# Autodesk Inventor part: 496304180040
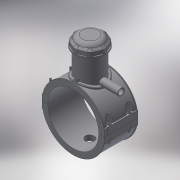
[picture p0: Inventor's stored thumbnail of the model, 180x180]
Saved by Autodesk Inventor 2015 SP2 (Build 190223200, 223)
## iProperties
Created: 2017-07
Part Number: 496304180040
Material: Generic
Description: PLASSON TAPPING SADDLE 180x40
Document SubType Name: Modeling
Designer: KIM
Mass: 1221.32 g
Surface Area: 2578.03 cm^2
Volume: 1221.32 cm^3
Density: 1 g/cm^3
Appearance: Default
Author: KIM
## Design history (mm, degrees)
derived "496304.ipt"
feature "Solid1::496304.ipt"
feature "Solid2::496304.ipt"
feature "Solid4::496304.ipt"
feature "Solid5::496304.ipt"
tag "TaggingFeature1"
body "Solid1"
body "Solid2"
other parameters: "B_" = 219, "L_" = 118, "d_t" = 6, "H_2" = 138, "H_1" = 21, "H_" = 155, "d1" = 205.2, "d148" = 2.7, "d160" = 2.7, "d169" = 3.375, "d192" = 6.3, "d2" = 219, "d3" = 45, "d4" = 118, "d5" = 0, "d6" = 0.1, "d8" = 0, "d19" = 6, "d20" = 6, "d21" = 70.8, "d23" = 0, "d24" = 35.4, "d26" = 0, "d29" = 3, "d31" = 6, "d32" = 0, "d33" = 0, "d34" = 0.6, "d40" = 106.704, "d41" = 72, "d43" = 0, "d45" = 0, "d47" = 173.4, "d70" = 15, "d72" = 0, "d73" = 6, "d75" = 5, "d76" = 0, "d77" = 9, "d79" = 15, "d80" = 47.2, "d82" = 5 deg, "d84" = 4, "d85" = 14, "d86" = 0, "d87" = 3, "d88" = 0, "d89" = 1, "d90" = 1, "d91" = 94.4, "d92" = 0, "d93" = 0.5, "d94" = 94.73684, "d96" = 209.304, "d97" = 2.36, "d98" = 0, "d102" = 1.8, "d120" = 140 deg, "d121" = 24.228, "d122" = 20 deg, "d123" = 410.4, "d124" = 123.12, "d126" = 0, "d143" = 185.4, "d145" = 19.38462, "d149" = 2.7, "d150" = 21.32308, "d153" = 118, "d154" = 0, "d156" = 102.6, "d157" = 160 deg, "d159" = 5.04, "d161" = 2.7, "d162" = 70.8, "d163" = 0, "d167" = 18, "d168" = 100.09756, "d170" = 3.375, "d172" = 0, "d173" = 1, "d176" = 20 deg, "d177" = 12.6, "d178" = 25.2, "d180" = 0, "d183" = 10.08, "d184" = 10.08, "d185" = 38.35, "d186" = 38.35, "d187" = 102.6, "d188" = 7.56, "d189" = 12.6, "d190" = 0, "d191" = 153.9, "d193" = 6.3, "d194" = 4.13, "d195" = 90 deg, "d197" = 0, "d199" = 0, "d200" = 12.6, "d202" = 0, "d203" = 138, "d204" = 68.4, "d205" = 50.4, "d206" = 61.2, "d207" = 103.5, "d208" = 107.64, "d209" = 128.34, "d210" = 61.92, "d211" = 72, "d212" = 57.6, "d213" = 0.9, "d216" = 0, "d217" = 18, "d218" = 18, "d219" = 3.6, "d224" = 0, "d230" = 3.6, "d233" = 6, "d236" = 109.5, "d237" = 35.4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
